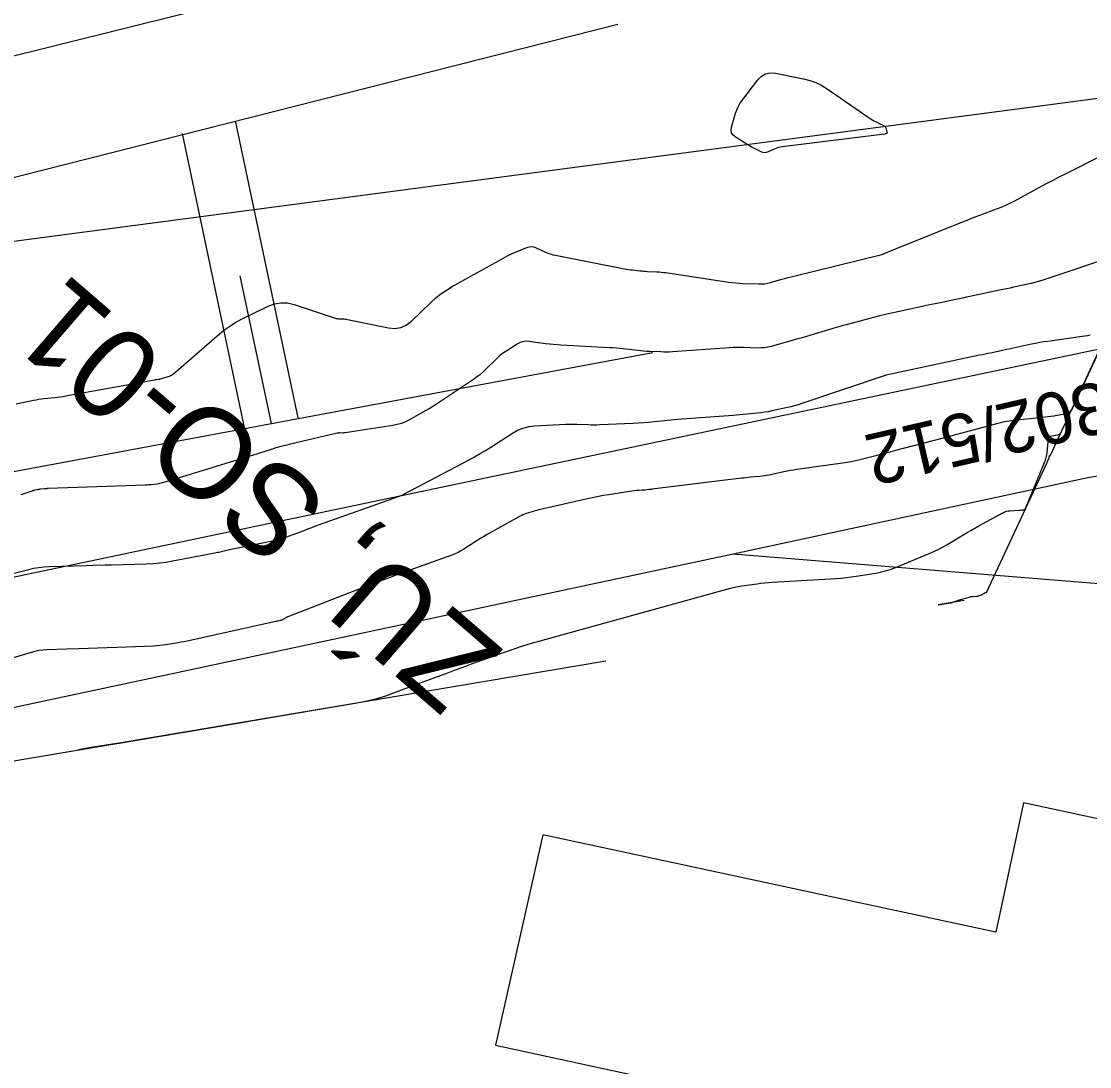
# Model space of a CAD drawing. Extents: x -534481 to -534262, y -1190577 to -1190138.
# Drawn here: x -534408.03 to -534390.37, y -1190542.27 to -1190524.99 of the extents above; entities that cross this region are included whole.
import ezdxf

# ---------------------------------------------------------------- set-up
doc = ezdxf.new("R2010")
doc.units = 0
for name, color, linetype in [('Bonity', 7, 'Continuous'), ('Definiční body', 7, 'Continuous'), ('Polygon budovy', 7, 'Continuous'), ('Polygon parcely', 7, 'Continuous'), ('Vrstva 18', 7, 'Continuous'), ('Vrstva 19', 7, 'Continuous'), ('Vrstva 31', 7, 'Continuous'), ('Vrstva 35', 7, 'Continuous'), ('Vrstva 36', 7, 'Continuous')]:
    doc.layers.add(name, color=color, linetype=linetype)

msp = doc.modelspace()

# ---------------------------------------------------------------- linework, layer by layer
at = {"layer": 'Bonity'}
msp.add_line((-534422.24, -1190529.075), (-534398.624, -1190523.185), dxfattribs=at)
at = {"layer": 'Definiční body'}
for points in [[(-534424.26, -1190537.56), (-534383.41, -1190528.98), (-534381.269, -1190528.899)], [(-534381.658, -1190531.109), (-534390.4, -1190532.54), (-534396.26, -1190533.8)], [(-534396.26, -1190533.8), (-534408.82, -1190536.48), (-534409.82, -1190536.63)], [(-534382.333, -1190534.934), (-534396.26, -1190533.8)]]:
    msp.add_lwpolyline(points, dxfattribs=at)
at = {"layer": 'Polygon parcely'}
msp.add_lwpolyline([(-534400.19, -1190541.92), (-534394.59, -1190543.13), (-534394.89, -1190544.51), (-534390.54, -1190545.47), (-534390.82, -1190546.76), (-534389.15, -1190547.11), (-534390.54, -1190553.66), (-534381.04, -1190555.72), (-534378.2, -1190543), (-534387.05, -1190541.1), (-534386.59, -1190538.96), (-534391.46, -1190537.91), (-534391.92, -1190540.05), (-534399.41, -1190538.44)], close=True, dxfattribs=at)
at = {"layer": 'Vrstva 18'}
msp.add_lwpolyline([(-534395.715, -1190527.162), (-534395.743, -1190527.165), (-534395.771, -1190527.161), (-534395.799, -1190527.151), (-534395.911, -1190527.096), (-534395.939, -1190527.082), (-534395.967, -1190527.067), (-534395.994, -1190527.052), (-534396.02, -1190527.035), (-534396.23, -1190526.901), (-534396.266, -1190526.87), (-534396.288, -1190526.834), (-534396.296, -1190526.792), (-534396.289, -1190526.745), (-534396.221, -1190526.51), (-534396.202, -1190526.456), (-534396.179, -1190526.404), (-534396.151, -1190526.354), (-534396.118, -1190526.307), (-534395.854, -1190525.96), (-534395.795, -1190525.899), (-534395.726, -1190525.86), (-534395.649, -1190525.844), (-534395.563, -1190525.851), (-534395.1, -1190525.944), (-534394.995, -1190525.971), (-534394.894, -1190526.007), (-534394.798, -1190526.054), (-534394.706, -1190526.111), (-534394.013, -1190526.59), (-534393.988, -1190526.607), (-534393.962, -1190526.622), (-534393.935, -1190526.637), (-534393.908, -1190526.651), (-534393.765, -1190526.719), (-534393.755, -1190526.725), (-534393.747, -1190526.733), (-534393.741, -1190526.742), (-534393.738, -1190526.753), (-534393.721, -1190526.82), (-534393.72, -1190526.828), (-534393.717, -1190526.839), (-534393.717, -1190526.842), (-534393.718, -1190526.844), (-534393.719, -1190526.845), (-534393.722, -1190526.846), (-534393.741, -1190526.854), (-534393.747, -1190526.855), (-534393.757, -1190526.858), (-534393.761, -1190526.859), (-534395.45, -1190527.067), (-534395.481, -1190527.072), (-534395.511, -1190527.079), (-534395.541, -1190527.089), (-534395.57, -1190527.101), (-534395.686, -1190527.153)], close=True, dxfattribs=at)
for points in [[(-534392.445, -1190534.57), (-534392.875, -1190534.642), (-534392.667, -1190534.607), (-534392.658, -1190534.605), (-534392.649, -1190534.603), (-534392.64, -1190534.6), (-534392.631, -1190534.597), (-534392.586, -1190534.581), (-534392.564, -1190534.572), (-534392.534, -1190534.561), (-534392.526, -1190534.559), (-534392.519, -1190534.556), (-534392.511, -1190534.554), (-534392.503, -1190534.552), (-534392.338, -1190534.506), (-534392.331, -1190534.504), (-534392.324, -1190534.503), (-534392.308, -1190534.501), (-534392.298, -1190534.5), (-534392.241, -1190534.497), (-534392.232, -1190534.496), (-534392.223, -1190534.495), (-534392.206, -1190534.492), (-534392.201, -1190534.491), (-534392.197, -1190534.49), (-534392.193, -1190534.489), (-534392.189, -1190534.487), (-534392.158, -1190534.474), (-534392.15, -1190534.471), (-534392.142, -1190534.466), (-534392.121, -1190534.454), (-534392.111, -1190534.448), (-534392.093, -1190534.438), (-534392.088, -1190534.437), (-534392.074, -1190534.436), (-534392.073, -1190534.435), (-534391.077, -1190532.296), (-534391.072, -1190532.287), (-534391.068, -1190532.277), (-534391.064, -1190532.268), (-534391.06, -1190532.259), (-534391.04, -1190532.209), (-534391.039, -1190532.206), (-534391.038, -1190532.202), (-534391.037, -1190532.198), (-534391.036, -1190532.194), (-534391.034, -1190532.176), (-534391.034, -1190532.174), (-534391.033, -1190532.172), (-534391.032, -1190532.171), (-534391.03, -1190532.171), (-534391.021, -1190532.169), (-534391.018, -1190532.168), (-534391.016, -1190532.165), (-534389.189, -1190528.244)], [(-534389.246, -1190528.366), (-534390.653, -1190531.386), (-534390.675, -1190531.423), (-534390.704, -1190531.452), (-534390.74, -1190531.473), (-534390.782, -1190531.485), (-534390.963, -1190531.518), (-534391.008, -1190531.526), (-534391.053, -1190531.533), (-534391.099, -1190531.538), (-534391.145, -1190531.543), (-534391.571, -1190531.586), (-534391.657, -1190531.596), (-534391.742, -1190531.61), (-534391.826, -1190531.627), (-534391.911, -1190531.648), (-534392.708, -1190531.862), (-534392.729, -1190531.867), (-534392.778, -1190531.88), (-534392.792, -1190531.883), (-534393.602, -1190532.094), (-534393.672, -1190532.113), (-534393.743, -1190532.131), (-534393.814, -1190532.15), (-534393.884, -1190532.168), (-534394.166, -1190532.243), (-534394.237, -1190532.26), (-534394.308, -1190532.276), (-534394.38, -1190532.289), (-534394.452, -1190532.3), (-534395.208, -1190532.403), (-534395.262, -1190532.411), (-534395.316, -1190532.42), (-534395.369, -1190532.43), (-534395.423, -1190532.441), (-534395.668, -1190532.493), (-534395.706, -1190532.501), (-534395.743, -1190532.507), (-534395.782, -1190532.513), (-534395.82, -1190532.517), (-534395.973, -1190532.531), (-534396.012, -1190532.534), (-534396.05, -1190532.538), (-534396.088, -1190532.543), (-534396.126, -1190532.547), (-534397.603, -1190532.729), (-534397.617, -1190532.731), (-534397.631, -1190532.732), (-534397.645, -1190532.734), (-534397.659, -1190532.735), (-534397.719, -1190532.741), (-534397.731, -1190532.742), (-534397.743, -1190532.743), (-534397.755, -1190532.744), (-534397.767, -1190532.744), (-534397.816, -1190532.747), (-534397.828, -1190532.747), (-534397.84, -1190532.748), (-534397.852, -1190532.75), (-534397.864, -1190532.751), (-534398.325, -1190532.82), (-534398.406, -1190532.833), (-534398.486, -1190532.848), (-534398.566, -1190532.863), (-534398.646, -1190532.881), (-534399.45, -1190533.064), (-534399.48, -1190533.071), (-534399.509, -1190533.079), (-534399.539, -1190533.087), (-534399.568, -1190533.096), (-534399.685, -1190533.132), (-534399.714, -1190533.142), (-534399.742, -1190533.154), (-534399.769, -1190533.166), (-534399.796, -1190533.18), (-534400.338, -1190533.483), (-534400.387, -1190533.51), (-534400.434, -1190533.539), (-534400.482, -1190533.568), (-534400.528, -1190533.598), (-534400.714, -1190533.719), (-534400.762, -1190533.748), (-534400.81, -1190533.774), (-534400.86, -1190533.797), (-534400.912, -1190533.818), (-534401.609, -1190534.068), (-534401.676, -1190534.092), (-534401.743, -1190534.116), (-534401.81, -1190534.14), (-534401.876, -1190534.164), (-534402.143, -1190534.262), (-534402.21, -1190534.287), (-534402.276, -1190534.312), (-534402.342, -1190534.337), (-534402.409, -1190534.363), (-534403.625, -1190534.838), (-534403.633, -1190534.841), (-534403.642, -1190534.845), (-534403.65, -1190534.85), (-534403.658, -1190534.854), (-534403.695, -1190534.878), (-534403.7, -1190534.881), (-534403.704, -1190534.883), (-534403.709, -1190534.885), (-534403.714, -1190534.887), (-534403.733, -1190534.894), (-534403.738, -1190534.896), (-534403.743, -1190534.897), (-534403.748, -1190534.899), (-534403.753, -1190534.9), (-534403.792, -1190534.907), (-534403.808, -1190534.91), (-534403.824, -1190534.913), (-534405.238, -1190535.228), (-534405.288, -1190535.238), (-534405.338, -1190535.249), (-534405.389, -1190535.258), (-534405.439, -1190535.267), (-534405.642, -1190535.3), (-534405.693, -1190535.308), (-534405.743, -1190535.314), (-534405.795, -1190535.318), (-534405.846, -1190535.321), (-534406.294, -1190535.337), (-534407.087, -1190535.365), (-534407.284, -1190535.372), (-534407.612, -1190535.384), (-534407.677, -1190535.388), (-534407.742, -1190535.396), (-534407.806, -1190535.409), (-534407.869, -1190535.426), (-534408.432, -1190535.594)], [(-534389.891, -1190528.852), (-534391.16, -1190529.276), (-534391.217, -1190529.294), (-534391.275, -1190529.31), (-534391.333, -1190529.325), (-534391.391, -1190529.339), (-534391.626, -1190529.389), (-534391.684, -1190529.402), (-534391.743, -1190529.415), (-534391.802, -1190529.427), (-534391.86, -1190529.439), (-534392.351, -1190529.543), (-534392.409, -1190529.555), (-534392.466, -1190529.567), (-534392.523, -1190529.579), (-534392.58, -1190529.591), (-534392.81, -1190529.639), (-534392.867, -1190529.651), (-534392.924, -1190529.663), (-534392.982, -1190529.675), (-534393.039, -1190529.688), (-534393.542, -1190529.794), (-534393.642, -1190529.816), (-534393.742, -1190529.839), (-534393.842, -1190529.864), (-534393.942, -1190529.89), (-534394.392, -1190530.009), (-534394.466, -1190530.029), (-534394.539, -1190530.05), (-534394.612, -1190530.071), (-534394.685, -1190530.092), (-534394.976, -1190530.18), (-534395.049, -1190530.201), (-534395.122, -1190530.223), (-534395.195, -1190530.244), (-534395.269, -1190530.265), (-534395.632, -1190530.366), (-534395.688, -1190530.38), (-534395.744, -1190530.389), (-534395.801, -1190530.393), (-534395.859, -1190530.394), (-534396.09, -1190530.386), (-534396.148, -1190530.384), (-534396.206, -1190530.385), (-534396.264, -1190530.386), (-534396.322, -1190530.39), (-534397.267, -1190530.457), (-534397.315, -1190530.46), (-534397.362, -1190530.461), (-534397.41, -1190530.461), (-534397.457, -1190530.459), (-534397.648, -1190530.451), (-534397.695, -1190530.449), (-534397.743, -1190530.445), (-534397.79, -1190530.441), (-534397.838, -1190530.436), (-534398.08, -1190530.408), (-534398.136, -1190530.402), (-534398.193, -1190530.397), (-534398.249, -1190530.392), (-534398.306, -1190530.389), (-534399.111, -1190530.346), (-534399.174, -1190530.342), (-534399.238, -1190530.337), (-534399.301, -1190530.33), (-534399.364, -1190530.323), (-534399.64, -1190530.286), (-534399.691, -1190530.283), (-534399.739, -1190530.289), (-534399.786, -1190530.304), (-534399.831, -1190530.328), (-534400.006, -1190530.439), (-534400.049, -1190530.468), (-534400.09, -1190530.498), (-534400.13, -1190530.531), (-534400.168, -1190530.567), (-534400.363, -1190530.757), (-534400.409, -1190530.8), (-534400.456, -1190530.84), (-534400.506, -1190530.878), (-534400.557, -1190530.914), (-534401.103, -1190531.279), (-534401.165, -1190531.32), (-534401.227, -1190531.359), (-534401.291, -1190531.397), (-534401.355, -1190531.434), (-534401.614, -1190531.579), (-534401.68, -1190531.612), (-534401.747, -1190531.639), (-534401.817, -1190531.659), (-534401.889, -1190531.674), (-534402.675, -1190531.796), (-534402.687, -1190531.797), (-534402.698, -1190531.798), (-534402.709, -1190531.799), (-534402.721, -1190531.799), (-534402.767, -1190531.798), (-534402.778, -1190531.799), (-534402.789, -1190531.799), (-534402.801, -1190531.801), (-534402.812, -1190531.803), (-534403.583, -1190531.983), (-534403.663, -1190532.003), (-534403.742, -1190532.024), (-534403.821, -1190532.046), (-534403.899, -1190532.07), (-534404.212, -1190532.169), (-534404.29, -1190532.194), (-534404.369, -1190532.218), (-534404.447, -1190532.243), (-534404.526, -1190532.266), (-534405.367, -1190532.521), (-534405.405, -1190532.532), (-534405.442, -1190532.544), (-534405.48, -1190532.555), (-534405.517, -1190532.567), (-534405.698, -1190532.623), (-534405.721, -1190532.63), (-534405.744, -1190532.635), (-534405.766, -1190532.639), (-534405.79, -1190532.643), (-534405.882, -1190532.653), (-534405.906, -1190532.656), (-534405.929, -1190532.658), (-534405.952, -1190532.659), (-534405.976, -1190532.66), (-534407.586, -1190532.718), (-534407.602, -1190532.718), (-534407.617, -1190532.719), (-534407.633, -1190532.721), (-534407.649, -1190532.722), (-534407.719, -1190532.729), (-534407.731, -1190532.73), (-534407.743, -1190532.732), (-534407.755, -1190532.734), (-534407.766, -1190532.736), (-534407.813, -1190532.746), (-534407.825, -1190532.749), (-534407.836, -1190532.752), (-534407.848, -1190532.755), (-534407.859, -1190532.759), (-534408.038, -1190532.821)], [(-534411.243, -1190537.736), (-534404.293, -1190536.566)]]:
    msp.add_lwpolyline(points, dxfattribs=at)
at = {"layer": 'Vrstva 19'}
for points in [[(-534408.116, -1190531.315), (-534407.831, -1190531.256), (-534407.787, -1190531.248), (-534407.743, -1190531.24), (-534407.698, -1190531.234), (-534407.654, -1190531.229), (-534407.475, -1190531.211), (-534407.431, -1190531.206), (-534407.386, -1190531.2), (-534407.342, -1190531.193), (-534407.298, -1190531.186), (-534405.832, -1190530.919), (-534405.823, -1190530.917), (-534405.814, -1190530.916), (-534405.806, -1190530.915), (-534405.797, -1190530.914), (-534405.756, -1190530.909), (-534405.749, -1190530.908), (-534405.743, -1190530.907), (-534405.737, -1190530.905), (-534405.731, -1190530.904), (-534405.695, -1190530.893), (-534405.683, -1190530.889), (-534405.584, -1190530.857), (-534405.566, -1190530.85), (-534405.549, -1190530.841), (-534405.533, -1190530.831), (-534405.518, -1190530.819), (-534404.755, -1190530.161), (-534404.665, -1190530.088), (-534404.57, -1190530.021), (-534404.472, -1190529.961), (-534404.37, -1190529.907), (-534403.952, -1190529.703), (-534403.847, -1190529.662), (-534403.74, -1190529.644), (-534403.632, -1190529.648), (-534403.522, -1190529.673), (-534402.84, -1190529.899), (-534402.824, -1190529.904), (-534402.808, -1190529.907), (-534402.792, -1190529.91), (-534402.775, -1190529.911), (-534402.708, -1190529.912), (-534402.691, -1190529.913), (-534402.674, -1190529.915), (-534402.658, -1190529.917), (-534402.641, -1190529.92), (-534401.962, -1190530.061), (-534401.856, -1190530.072), (-534401.758, -1190530.057), (-534401.667, -1190530.017), (-534401.583, -1190529.952), (-534401.262, -1190529.641), (-534401.18, -1190529.566), (-534401.093, -1190529.498), (-534401.002, -1190529.435), (-534400.907, -1190529.377), (-534400.034, -1190528.891), (-534399.992, -1190528.868), (-534399.949, -1190528.847), (-534399.906, -1190528.827), (-534399.862, -1190528.808), (-534399.676, -1190528.731), (-534399.636, -1190528.719), (-534399.597, -1190528.715), (-534399.558, -1190528.721), (-534399.519, -1190528.735), (-534399.363, -1190528.808), (-534399.324, -1190528.825), (-534399.284, -1190528.839), (-534399.243, -1190528.851), (-534399.201, -1190528.861), (-534398.056, -1190529.083), (-534398.025, -1190529.089), (-534397.994, -1190529.094), (-534397.962, -1190529.099), (-534397.931, -1190529.102), (-534397.806, -1190529.117), (-534397.774, -1190529.12), (-534397.743, -1190529.123), (-534397.712, -1190529.125), (-534397.68, -1190529.127), (-534397.524, -1190529.134), (-534397.487, -1190529.136), (-534397.451, -1190529.139), (-534397.414, -1190529.143), (-534397.378, -1190529.148), (-534396.337, -1190529.303), (-534396.278, -1190529.311), (-534396.219, -1190529.317), (-534396.16, -1190529.322), (-534396.1, -1190529.325), (-534395.843, -1190529.334), (-534395.793, -1190529.334), (-534395.744, -1190529.33), (-534395.695, -1190529.322), (-534395.647, -1190529.31), (-534395.455, -1190529.256), (-534395.406, -1190529.243), (-534395.358, -1190529.23), (-534395.31, -1190529.217), (-534395.261, -1190529.205), (-534393.805, -1190528.848), (-534393.798, -1190528.846), (-534393.792, -1190528.844), (-534393.786, -1190528.842), (-534393.779, -1190528.839), (-534393.752, -1190528.826), (-534393.743, -1190528.822), (-534393.734, -1190528.818), (-534393.701, -1190528.805), (-534393.697, -1190528.804), (-534392.479, -1190528.313), (-534392.406, -1190528.284), (-534392.333, -1190528.255), (-534392.259, -1190528.227), (-534392.186, -1190528.199), (-534391.891, -1190528.089), (-534391.817, -1190528.06), (-534391.745, -1190528.029), (-534391.675, -1190527.995), (-534391.605, -1190527.959), (-534391.165, -1190527.72), (-534391.069, -1190527.668), (-534390.972, -1190527.617), (-534390.874, -1190527.566), (-534390.777, -1190527.517), (-534390.131, -1190527.193)], [(-534398.369, -1190535.568), (-534406.383, -1190536.918), (-534406.909, -1190537.006), (-534407.085, -1190537.036), (-534406.909, -1190537.006), (-534406.383, -1190536.918), (-534402.51, -1190536.265), (-534402.34, -1190536.232), (-534402.172, -1190536.191), (-534402.006, -1190536.142), (-534401.843, -1190536.085), (-534401.148, -1190535.824), (-534401.008, -1190535.772), (-534400.868, -1190535.72), (-534400.728, -1190535.668), (-534400.587, -1190535.617), (-534400.024, -1190535.414), (-534399.883, -1190535.364), (-534399.741, -1190535.317), (-534399.598, -1190535.273), (-534399.455, -1190535.232), (-534396.365, -1190534.378), (-534396.304, -1190534.362), (-534396.242, -1190534.349), (-534396.18, -1190534.337), (-534396.118, -1190534.327), (-534395.868, -1190534.291), (-534395.806, -1190534.283), (-534395.743, -1190534.276), (-534395.68, -1190534.271), (-534395.617, -1190534.266), (-534394.558, -1190534.203), (-534394.476, -1190534.198), (-534394.394, -1190534.19), (-534394.313, -1190534.179), (-534394.231, -1190534.167), (-534393.906, -1190534.114), (-534393.825, -1190534.099), (-534393.746, -1190534.079), (-534393.667, -1190534.054), (-534393.591, -1190534.025), (-534393.021, -1190533.792), (-534392.942, -1190533.758), (-534392.864, -1190533.721), (-534392.788, -1190533.68), (-534392.713, -1190533.637), (-534392.396, -1190533.446), (-534392.332, -1190533.408), (-534392.267, -1190533.371), (-534392.202, -1190533.334), (-534392.137, -1190533.299), (-534391.793, -1190533.113), (-534391.768, -1190533.101), (-534391.741, -1190533.092), (-534391.714, -1190533.086), (-534391.686, -1190533.083), (-534391.536, -1190533.073), (-534391.516, -1190533.072), (-534391.496, -1190533.07), (-534391.455, -1190533.067), (-534391.446, -1190533.065), (-534391.438, -1190533.061), (-534391.432, -1190533.055), (-534391.427, -1190533.046), (-534391.114, -1190532.285), (-534391.099, -1190532.244), (-534391.087, -1190532.202), (-534391.078, -1190532.159), (-534391.072, -1190532.116), (-534391.049, -1190531.901), (-534391.043, -1190531.879), (-534391.033, -1190531.863), (-534391.017, -1190531.851), (-534390.996, -1190531.844), (-534390.902, -1190531.827), (-534390.88, -1190531.821), (-534390.861, -1190531.81), (-534390.846, -1190531.795), (-534390.834, -1190531.775), (-534389.814, -1190529.586)], [(-534408.239, -1190534.14), (-534407.908, -1190534.054), (-534407.825, -1190534.035), (-534407.742, -1190534.02), (-534407.657, -1190534.011), (-534407.572, -1190534.006), (-534406.955, -1190533.989), (-534406.851, -1190533.986), (-534406.643, -1190533.98), (-534406.539, -1190533.977), (-534405.959, -1190533.961), (-534405.852, -1190533.956), (-534405.744, -1190533.946), (-534405.637, -1190533.932), (-534405.531, -1190533.914), (-534404.857, -1190533.784), (-534404.834, -1190533.78), (-534404.812, -1190533.775), (-534404.79, -1190533.771), (-534404.768, -1190533.766), (-534404.679, -1190533.746), (-534404.657, -1190533.741), (-534404.634, -1190533.736), (-534404.612, -1190533.731), (-534404.59, -1190533.727), (-534403.878, -1190533.582), (-534403.811, -1190533.567), (-534403.745, -1190533.55), (-534403.679, -1190533.529), (-534403.614, -1190533.506), (-534403.357, -1190533.408), (-534403.293, -1190533.384), (-534403.228, -1190533.36), (-534403.163, -1190533.336), (-534403.099, -1190533.313), (-534401.795, -1190532.848), (-534401.779, -1190532.843), (-534401.751, -1190532.834), (-534401.743, -1190532.831), (-534401.736, -1190532.827), (-534401.713, -1190532.814), (-534401.705, -1190532.81), (-534400.628, -1190532.241), (-534400.536, -1190532.192), (-534400.446, -1190532.14), (-534400.357, -1190532.087), (-534400.268, -1190532.031), (-534399.912, -1190531.802), (-534399.826, -1190531.754), (-534399.735, -1190531.717), (-534399.641, -1190531.693), (-534399.542, -1190531.682), (-534399.035, -1190531.653), (-534398.988, -1190531.651), (-534398.94, -1190531.65), (-534398.893, -1190531.65), (-534398.846, -1190531.652), (-534398.658, -1190531.66), (-534398.61, -1190531.662), (-534398.563, -1190531.662), (-534398.516, -1190531.662), (-534398.469, -1190531.66), (-534397.922, -1190531.634), (-534397.832, -1190531.63), (-534397.743, -1190531.624), (-534397.654, -1190531.617), (-534397.565, -1190531.609), (-534397.184, -1190531.572), (-534397.108, -1190531.565), (-534397.031, -1190531.558), (-534396.954, -1190531.552), (-534396.877, -1190531.547), (-534396.569, -1190531.527), (-534396.492, -1190531.521), (-534396.415, -1190531.516), (-534396.338, -1190531.509), (-534396.261, -1190531.502), (-534395.871, -1190531.467), (-534395.807, -1190531.46), (-534395.744, -1190531.451), (-534395.68, -1190531.441), (-534395.618, -1190531.428), (-534395.366, -1190531.374), (-534395.304, -1190531.359), (-534395.242, -1190531.343), (-534395.18, -1190531.325), (-534395.119, -1190531.306), (-534393.759, -1190530.846), (-534393.751, -1190530.843), (-534393.736, -1190530.84), (-534393.734, -1190530.839), (-534392.187, -1190530.509), (-534392.142, -1190530.499), (-534392.098, -1190530.49), (-534392.054, -1190530.48), (-534392.009, -1190530.471), (-534391.832, -1190530.433), (-534391.787, -1190530.424), (-534391.743, -1190530.415), (-534391.699, -1190530.405), (-534391.654, -1190530.396), (-534391.332, -1190530.326), (-534391.264, -1190530.312), (-534391.195, -1190530.299), (-534391.126, -1190530.288), (-534391.057, -1190530.278), (-534390.491, -1190530.199), (-534390.446, -1190530.192), (-534390.402, -1190530.184), (-534390.358, -1190530.174)]]:
    msp.add_lwpolyline(points, dxfattribs=at)
at = {"layer": 'Vrstva 31'}
msp.add_lwpolyline([(-534380.58, -1190524.995), (-534412.047, -1190529.146), (-534410.245, -1190529.642)], dxfattribs=at)
at = {"layer": 'Vrstva 35'}
for p, q in [((-534421.77, -1190531.02), (-534398.17, -1190525.04)), ((-534427.69, -1190536.07), (-534397.59, -1190530.47))]:
    msp.add_line(p, q, dxfattribs=at)
at = {"layer": 'Vrstva 36'}
for p, q in [((-534403.454, -1190531.55), (-534404.487, -1190526.659)), ((-534404.335, -1190531.736), (-534405.368, -1190526.845)), ((-534403.895, -1190531.643), (-534404.411, -1190529.198))]:
    msp.add_line(p, q, dxfattribs=at)

# ---------------------------------------------------------------- texts
at = {"layer": 'Polygon budovy'}
msp.add_text('2302/512', height=0.85, rotation=193, dxfattribs=at).set_placement((-534389.518, -1190530.781))
at = {"layer": 'Vrstva 31'}
msp.add_text('ZÚ, SO-01', height=1.5, rotation=139.2051, dxfattribs=at).set_placement((-534400.02, -1190535.416))

doc.saveas('drawing.dxf')
